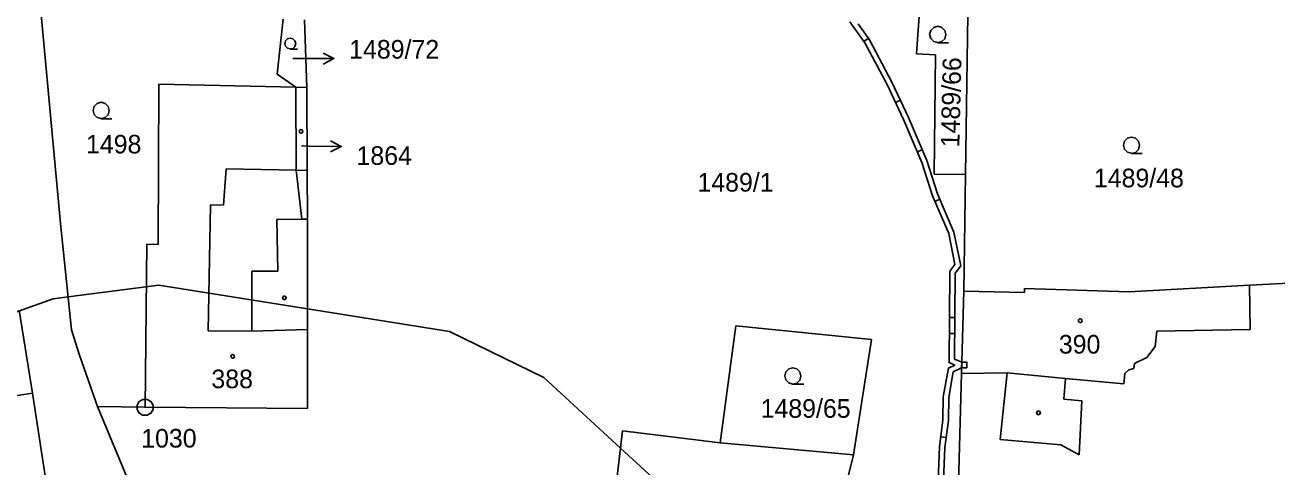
# Model space of a CAD drawing. Extents: x -779618 to -776429, y -1144546 to -1143350.
# Drawn here: x -777488.2 to -777373.9, y -1143974.1 to -1143933.7 of the extents above; entities that cross this region are included whole.
import ezdxf

# ---------------------------------------------------------------- set-up
doc = ezdxf.new("R2010")
doc.units = 0
for name, color, linetype in [('1', 7, 'Continuous'), ('11', 7, 'Continuous'), ('12', 7, 'Continuous'), ('13', 7, 'Continuous'), ('2', 7, 'Continuous'), ('3', 7, 'Continuous'), ('4', 7, 'Continuous'), ('5', 7, 'Continuous'), ('7', 7, 'Continuous'), ('8', 7, 'Continuous')]:
    doc.layers.add(name, color=color, linetype=linetype)

msp = doc.modelspace()

# ---------------------------------------------------------------- linework, layer by layer
at = {"layer": '1'}
for p, q in [((-777484.96, -1143951.84), (-777486.85, -1143931.42)), ((-777464.65, -1143933.18), (-777465.2, -1143938.21)), ((-777462.69, -1143933.25), (-777462.49, -1143939.42)), ((-777406.57, -1143932.89), (-777406.8, -1143936.33)), ((-777402.33, -1143947.36), (-777402.11, -1143932.75)), ((-777406.8, -1143936.33), (-777405.06, -1143936.43)), ((-777405.06, -1143936.43), (-777405.2, -1143947.32)), ((-777476.05, -1143953.74), (-777476, -1143939.12)), ((-777476, -1143939.12), (-777463.49, -1143939.4)), ((-777465.2, -1143938.21), (-777463.49, -1143939.4)), ((-777463.49, -1143939.4), (-777463.45, -1143946.96)), ((-777463.49, -1143939.4), (-777462.49, -1143939.42)), ((-777462.49, -1143939.42), (-777462.45, -1143946.98)), ((-777462.93, -1143951.45), (-777463.45, -1143946.96)), ((-777462.45, -1143946.98), (-777462.43, -1143951.45)), ((-777405.2, -1143947.32), (-777402.33, -1143947.36)), ((-777402.5, -1143958.01), (-777402.33, -1143947.36)), ((-777462.93, -1143951.45), (-777462.43, -1143951.45)), ((-777462.43, -1143951.45), (-777462.41, -1143961.51)), ((-777483.95, -1143961.55), (-777484.96, -1143951.84)), ((-777477.24, -1143968.59), (-777477.1, -1143953.73)), ((-777477.1, -1143953.73), (-777476.05, -1143953.74)), ((-777372.24, -1143957.25), (-777376.4, -1143957.46)), ((-777402.5, -1143958.01), (-777402.7, -1143965.53)), ((-777396.94, -1143958.12), (-777402.5, -1143958.01)), ((-777396.94, -1143957.77), (-777396.94, -1143958.12)), ((-777387.4, -1143958.06), (-777396.94, -1143957.77)), ((-777387.4, -1143958.06), (-777376.4, -1143957.46)), ((-777488.73, -1143959.74), (-777487.53, -1143967.33)), ((-777483.22, -1143963.84), (-777483.95, -1143961.55)), ((-777462.41, -1143961.51), (-777462.41, -1143968.73)), ((-777423.31, -1143961.18), (-777424.73, -1143971.85)), ((-777410.93, -1143962.41), (-777423.31, -1143961.18)), ((-777412.57, -1143972.94), (-777410.93, -1143962.41)), ((-777481.58, -1143968.55), (-777483.22, -1143963.84)), ((-777402.7, -1143965.53), (-777403.13, -1143981.77)), ((-777487.53, -1143967.33), (-777485.45, -1143980.98)), ((-777477.24, -1143968.59), (-777481.58, -1143968.55)), ((-777481.58, -1143968.55), (-777477.17, -1143979.2)), ((-777477.24, -1143968.59), (-777462.41, -1143968.73)), ((-777434.18, -1143975.17), (-777433.65, -1143970.77)), ((-777433.65, -1143970.77), (-777424.73, -1143971.85)), ((-777424.73, -1143971.85), (-777412.57, -1143972.94)), ((-777412.57, -1143972.94), (-777416.17, -1143987.69))]:
    msp.add_line(p, q, dxfattribs=at)
at = {"layer": '11'}
msp.add_lwpolyline([(-777497.86, -1143963.05), (-777488.72, -1143959.81), (-777485.63, -1143958.72), (-777484.26, -1143958.54), (-777475.98, -1143957.45), (-777462.41, -1143959.62), (-777449.46, -1143961.7), (-777440.85, -1143965.89), (-777433.84, -1143972.33), (-777430.9, -1143975.03), (-777425.62, -1143980.19), (-777422.96, -1143987.95), (-777418.25, -1143996.24), (-777416.15, -1143999.94), (-777406.09, -1144025.39), (-777404.74, -1144044.7), (-777404.15, -1144050.11)], dxfattribs=at)
at = {"layer": '12'}
for p, q in [((-777476.05, -1143953.74), (-777476, -1143939.12)), ((-777476, -1143939.12), (-777463.49, -1143939.4)), ((-777463.49, -1143939.4), (-777462.49, -1143939.42)), ((-777463.49, -1143939.4), (-777463.45, -1143946.96)), ((-777463.49, -1143939.4), (-777463.45, -1143946.96)), ((-777462.49, -1143939.42), (-777462.45, -1143946.98)), ((-777469.85, -1143946.85), (-777470.1, -1143950.16)), ((-777469.85, -1143946.85), (-777463.45, -1143946.96)), ((-777462.45, -1143946.98), (-777463.45, -1143946.96)), ((-777471.27, -1143950.14), (-777471.5, -1143961.64)), ((-777470.1, -1143950.16), (-777471.27, -1143950.14)), ((-777477.24, -1143968.59), (-777477.1, -1143953.73)), ((-777477.1, -1143953.73), (-777476.05, -1143953.74)), ((-777402.5, -1143958.01), (-777402.7, -1143965.53)), ((-777396.94, -1143958.12), (-777402.5, -1143958.01)), ((-777387.4, -1143958.06), (-777396.94, -1143957.77)), ((-777396.94, -1143957.77), (-777396.94, -1143958.12)), ((-777387.4, -1143958.06), (-777376.4, -1143957.46)), ((-777376.35, -1143961.5), (-777376.4, -1143957.46)), ((-777471.5, -1143961.64), (-777467.5, -1143961.67)), ((-777467.5, -1143961.67), (-777462.41, -1143961.51)), ((-777462.41, -1143961.51), (-777462.41, -1143968.73)), ((-777385.03, -1143963.06), (-777384.86, -1143961.67)), ((-777384.86, -1143961.67), (-777376.35, -1143961.5)), ((-777385.03, -1143963.06), (-777385.78, -1143964.07)), ((-777385.78, -1143964.07), (-777386.91, -1143964.61)), ((-777387.78, -1143965.53), (-777387.43, -1143965.19)), ((-777387.43, -1143965.19), (-777386.96, -1143965.08)), ((-777386.91, -1143964.61), (-777386.96, -1143965.08)), ((-777398.52, -1143965.48), (-777402.7, -1143965.53)), ((-777398.52, -1143965.48), (-777393.19, -1143965.98)), ((-777393.19, -1143965.98), (-777387.87, -1143966.47)), ((-777387.78, -1143965.53), (-777387.87, -1143966.47)), ((-777477.24, -1143968.59), (-777462.41, -1143968.73))]:
    msp.add_line(p, q, dxfattribs=at)
at = {"layer": '13'}
for p, q in [((-777411.62, -1143935.22), (-777411.21, -1143934.93)), ((-777408.28, -1143940.58), (-777408.73, -1143940.79)), ((-777406.73, -1143945.29), (-777406.27, -1143945.09)), ((-777404.68, -1143949.61), (-777405.14, -1143949.81)), ((-777403.8, -1143960.4), (-777403.3, -1143960.41)), ((-777403.31, -1143961.87), (-777403.81, -1143961.87)), ((-777404.59, -1143971.3), (-777404.1, -1143971.37))]:
    msp.add_line(p, q, dxfattribs=at)
for points in [[(-777408, -1143942.35), (-777409.49, -1143939.15), (-777411.53, -1143935.34), (-777412.89, -1143933.42)], [(-777412.15, -1143933.6), (-777411.11, -1143935.08), (-777409.05, -1143938.93), (-777407.54, -1143942.15)], [(-777403.87, -1143952.75), (-777405.34, -1143949.32), (-777406.31, -1143946.25), (-777408, -1143942.35)], [(-777407.54, -1143942.15), (-777405.85, -1143946.07), (-777404.88, -1143949.14), (-777403.39, -1143952.61)], [(-777403.77, -1143956.19), (-777403.31, -1143955.59), (-777403.87, -1143952.75)], [(-777403.39, -1143952.61), (-777402.77, -1143955.71), (-777403.27, -1143956.37)], [(-777404.36, -1143967.67), (-777403.89, -1143965.03), (-777403.32, -1143964.76), (-777403.83, -1143964.53), (-777403.77, -1143956.19)], [(-777403.27, -1143956.37), (-777403.33, -1143964.21), (-777402.67, -1143964.5), (-777402.69, -1143965.01), (-777403.45, -1143965.37), (-777403.86, -1143967.71)], [(-777404.2, -1143979.19), (-777404.9, -1143976.83), (-777404.71, -1143972.23), (-777404.4, -1143969.77), (-777404.36, -1143967.67)], [(-777403.86, -1143967.71), (-777403.9, -1143969.81), (-777404.21, -1143972.27), (-777404.4, -1143976.77), (-777403.72, -1143979.03)]]:
    msp.add_lwpolyline(points, dxfattribs=at)
msp.add_lwpolyline([(-777402.67, -1143964.5), (-777402.21, -1143964.5), (-777402.22, -1143965), (-777402.69, -1143965.01)], close=True, dxfattribs=at)
at = {"layer": '3'}
for points in [[(-777404.86, -1143935.31), (-777405.24, -1143935.21), (-777405.51, -1143934.94), (-777405.61, -1143934.57), (-777405.51, -1143934.2), (-777405.24, -1143933.93), (-777404.87, -1143933.83), (-777404.5, -1143933.93), (-777404.23, -1143934.2), (-777404.13, -1143934.58), (-777404.23, -1143934.96), (-777404.5, -1143935.23), (-777404.88, -1143935.33), (-777403.88, -1143935.33)], [(-777463.98, -1143935.9), (-777464.23, -1143935.83), (-777464.42, -1143935.65), (-777464.48, -1143935.4), (-777464.42, -1143935.16), (-777464.23, -1143934.98), (-777463.99, -1143934.91), (-777463.74, -1143934.98), (-777463.56, -1143935.16), (-777463.49, -1143935.41), (-777463.56, -1143935.67), (-777463.74, -1143935.85), (-777463.99, -1143935.91), (-777463.32, -1143935.91)], [(-777481.25, -1143942.25), (-777481.63, -1143942.15), (-777481.9, -1143941.88), (-777482, -1143941.51), (-777481.9, -1143941.14), (-777481.63, -1143940.87), (-777481.26, -1143940.77), (-777480.89, -1143940.87), (-777480.62, -1143941.14), (-777480.52, -1143941.52), (-777480.62, -1143941.9), (-777480.89, -1143942.17), (-777481.27, -1143942.27), (-777480.27, -1143942.27)], [(-777387.17, -1143945.42), (-777387.55, -1143945.32), (-777387.82, -1143945.05), (-777387.92, -1143944.68), (-777387.82, -1143944.31), (-777387.55, -1143944.04), (-777387.18, -1143943.94), (-777386.81, -1143944.04), (-777386.54, -1143944.31), (-777386.44, -1143944.69), (-777386.54, -1143945.07), (-777386.81, -1143945.34), (-777387.19, -1143945.44), (-777386.19, -1143945.44)], [(-777418.09, -1143966.49), (-777418.47, -1143966.39), (-777418.74, -1143966.12), (-777418.84, -1143965.75), (-777418.74, -1143965.38), (-777418.47, -1143965.11), (-777418.1, -1143965.01), (-777417.73, -1143965.11), (-777417.46, -1143965.38), (-777417.36, -1143965.76), (-777417.46, -1143966.14), (-777417.73, -1143966.41), (-777418.11, -1143966.51), (-777417.11, -1143966.51)]]:
    msp.add_lwpolyline(points, dxfattribs=at)
at = {"layer": '4'}
for p, q in [((-777469.85, -1143946.85), (-777470.1, -1143950.16)), ((-777469.85, -1143946.85), (-777463.45, -1143946.96)), ((-777462.45, -1143946.98), (-777463.45, -1143946.96)), ((-777471.27, -1143950.14), (-777471.5, -1143961.64)), ((-777470.1, -1143950.16), (-777471.27, -1143950.14)), ((-777462.93, -1143951.45), (-777465.23, -1143951.47)), ((-777465.13, -1143956.19), (-777465.23, -1143951.47)), ((-777467.51, -1143956.2), (-777465.13, -1143956.19)), ((-777467.5, -1143961.67), (-777467.51, -1143956.2)), ((-777376.35, -1143961.5), (-777376.4, -1143957.46)), ((-777471.5, -1143961.64), (-777467.5, -1143961.67)), ((-777467.5, -1143961.67), (-777462.41, -1143961.51)), ((-777385.03, -1143963.06), (-777384.86, -1143961.67)), ((-777384.86, -1143961.67), (-777376.35, -1143961.5)), ((-777385.03, -1143963.06), (-777385.78, -1143964.07)), ((-777385.78, -1143964.07), (-777386.91, -1143964.61)), ((-777387.78, -1143965.53), (-777387.43, -1143965.19)), ((-777387.43, -1143965.19), (-777386.96, -1143965.08)), ((-777386.91, -1143964.61), (-777386.96, -1143965.08)), ((-777398.52, -1143965.48), (-777402.7, -1143965.53)), ((-777398.52, -1143965.48), (-777399.16, -1143971.54)), ((-777398.52, -1143965.48), (-777393.19, -1143965.98)), ((-777393.19, -1143965.98), (-777393.36, -1143967.87)), ((-777393.19, -1143965.98), (-777387.87, -1143966.47)), ((-777387.78, -1143965.53), (-777387.87, -1143966.47)), ((-777490.3, -1143967.75), (-777487.53, -1143967.33)), ((-777391.7, -1143968.02), (-777393.36, -1143967.87)), ((-777391.97, -1143972.95), (-777391.7, -1143968.02)), ((-777399.16, -1143971.54), (-777393.63, -1143972.04)), ((-777393.63, -1143972.04), (-777391.97, -1143972.95))]:
    msp.add_line(p, q, dxfattribs=at)
at = {"layer": '5'}
for points in [[(-777463.01, -1143943.26), (-777462.91, -1143943.28), (-777462.86, -1143943.37), (-777462.84, -1143943.43), (-777462.86, -1143943.52), (-777462.94, -1143943.59), (-777463.01, -1143943.6), (-777463.1, -1143943.57), (-777463.16, -1143943.51), (-777463.18, -1143943.43), (-777463.16, -1143943.34), (-777463.08, -1143943.27)], [(-777464.44, -1143958.47), (-777464.35, -1143958.62), (-777464.44, -1143958.77), (-777464.62, -1143958.77), (-777464.71, -1143958.62), (-777464.62, -1143958.47)], [(-777391.86, -1143960.54), (-777391.76, -1143960.56), (-777391.71, -1143960.65), (-777391.69, -1143960.71), (-777391.71, -1143960.8), (-777391.79, -1143960.87), (-777391.86, -1143960.88), (-777391.95, -1143960.85), (-777392.01, -1143960.79), (-777392.03, -1143960.71), (-777392.01, -1143960.62), (-777391.93, -1143960.55)], [(-777469.25, -1143963.8), (-777469.15, -1143963.82), (-777469.1, -1143963.91), (-777469.08, -1143963.97), (-777469.1, -1143964.06), (-777469.18, -1143964.13), (-777469.25, -1143964.14), (-777469.34, -1143964.11), (-777469.4, -1143964.05), (-777469.42, -1143963.97), (-777469.4, -1143963.88), (-777469.32, -1143963.81)], [(-777395.59, -1143968.98), (-777395.5, -1143969.13), (-777395.59, -1143969.28), (-777395.77, -1143969.28), (-777395.86, -1143969.13), (-777395.77, -1143968.98)]]:
    msp.add_lwpolyline(points, close=True, dxfattribs=at)
at = {"layer": '7'}
for p, q in [((-777463.76, -1143936.78), (-777463, -1143936.78)), ((-777460, -1143936.78), (-777463, -1143936.78)), ((-777462.95, -1143944.75), (-777462.33, -1143944.76)), ((-777459.33, -1143944.79), (-777462.33, -1143944.76))]:
    msp.add_line(p, q, dxfattribs=at)
for points in [[(-777461, -1143936.28), (-777460, -1143936.78), (-777461, -1143937.28)], [(-777460.33, -1143944.28), (-777459.33, -1143944.79), (-777460.33, -1143945.28)]]:
    msp.add_lwpolyline(points, dxfattribs=at)
at = {"layer": '8'}
msp.add_line((-777477.29, -1143968.61), (-777477.19, -1143968.61), dxfattribs=at)
msp.add_lwpolyline([(-777477.05, -1143967.89), (-777476.71, -1143968.08), (-777476.52, -1143968.42), (-777476.52, -1143968.81), (-777476.71, -1143969.15), (-777477.05, -1143969.34), (-777477.44, -1143969.34), (-777477.78, -1143969.15), (-777477.97, -1143968.81), (-777477.97, -1143968.42), (-777477.78, -1143968.08), (-777477.44, -1143967.89)], close=True, dxfattribs=at)

# ---------------------------------------------------------------- texts
at = {"layer": '2'}
for s, height, p in [('1489/72', 0.1, (-777463.74, -1143936.78)), ('1498', 1.7, (-777482.64, -1143945.44)), ('1864', 0.1, (-777462.93, -1143944.75)), ('1489/1', 1.7, (-777426.81, -1143948.92)), ('1489/48', 1.7, (-777390.61, -1143948.53)), ('390', 1.7, (-777393.81, -1143963.71)), ('388', 1.7, (-777471.19, -1143966.87)), ('1489/65', 1.7, (-777421.04, -1143969.57))]:
    msp.add_text(s, height=height, dxfattribs=at).set_placement(p)
msp.add_text('1489/66', height=1.7, rotation=88.6366, dxfattribs=at).set_placement((-777402.9, -1143944.89))
at = {"layer": '7'}
for s, p in [('1489/72', (-777458.61, -1143936.78)), ('1864', (-777457.94, -1143946.48))]:
    msp.add_text(s, height=1.7, dxfattribs=at).set_placement(p)
at = {"layer": '8'}
msp.add_text('1030', height=1.7, dxfattribs=at).set_placement((-777477.6, -1143972.29))

doc.saveas('drawing.dxf')
